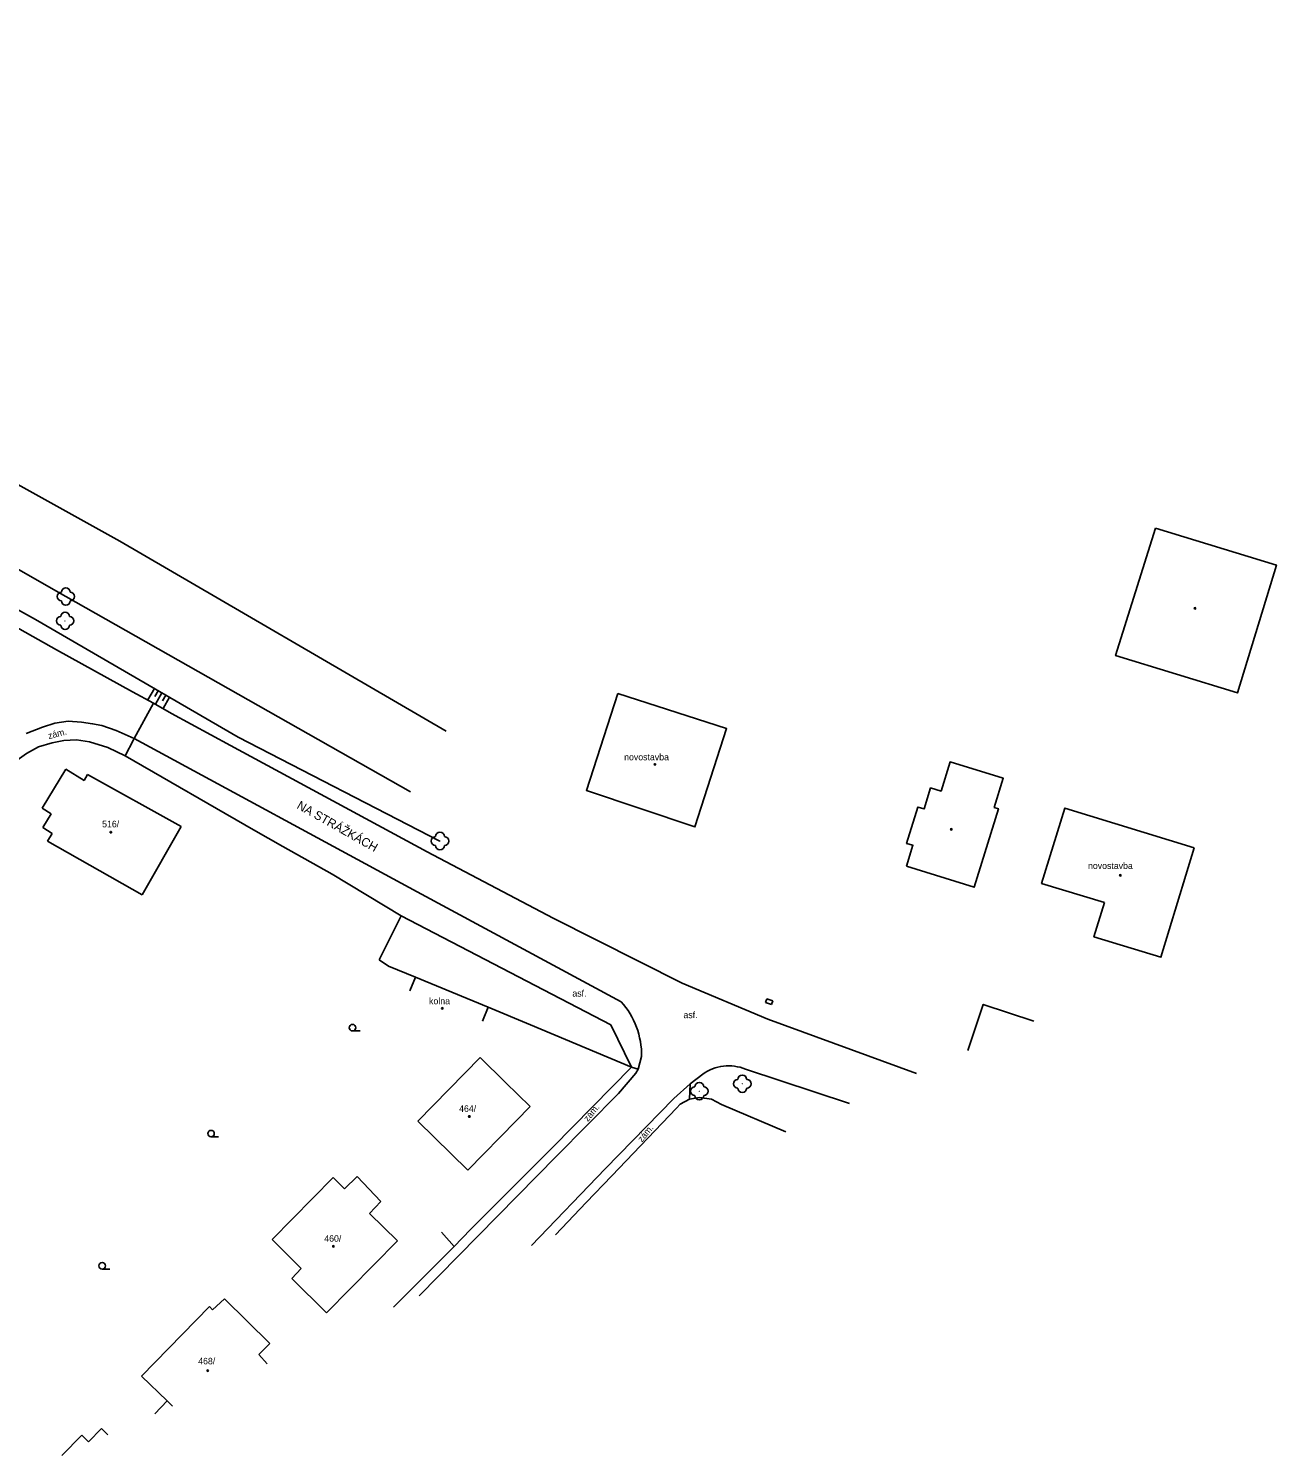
# Model space of a CAD drawing. Extents: x -737488 to -734267, y -1145775 to -1142573.
# Drawn here: x -736465.6 to -736322.7, y -1144292.3 to -1144128.9 of the extents above; entities that cross this region are included whole.
import ezdxf

# ---------------------------------------------------------------- set-up
doc = ezdxf.new("R2010")
doc.units = 0
for name, color, linetype in [('Vrstva 1', 7, 'Continuous'), ('Vrstva 10', 7, 'Continuous'), ('Vrstva 11', 7, 'Continuous'), ('Vrstva 12', 7, 'Continuous'), ('Vrstva 13', 7, 'Continuous'), ('Vrstva 14', 7, 'Continuous'), ('Vrstva 3', 7, 'Continuous'), ('Vrstva 4', 7, 'Continuous'), ('Vrstva 5', 7, 'Continuous'), ('Vrstva 6', 7, 'Continuous'), ('Vrstva 8', 7, 'Continuous'), ('Vrstva 9', 7, 'Continuous')]:
    doc.layers.add(name, color=color, linetype=linetype)

# ---------------------------------------------------------------- blocks, each defined once
blk = doc.blocks.new('3.130')
at = {"layer": 'Vrstva 1'}
blk.add_circle((0, 0), 0.001, dxfattribs=at)
for centre, start, end in [((-1, 0), 90, 270), ((0, 1), 0, 180), ((1, 0), 270, 90), ((0, -1), 180, 360)]:
    blk.add_arc(centre, 1, start, end, dxfattribs=at)
blk = doc.blocks.new('3.040')
at = {"layer": 'Vrstva 1'}
blk.add_line((0, -0.75), (1.75, -0.75), dxfattribs=at)
blk.add_circle((0, 0), 0.75, dxfattribs=at)
blk = doc.blocks.new('4.020')
at = {"layer": 'Vrstva 1'}
blk.add_circle((0, 0), 0.175, dxfattribs=at)

msp = doc.modelspace()

# ---------------------------------------------------------------- linework, layer by layer
at = {"layer": 'Vrstva 10'}
for points in [[(-736462.4, -1144200.02), (-736481.94, -1144189.02), (-736496.2, -1144180.94)], [(-736442.48, -1144210.96), (-736449.24, -1144207.31), (-736451.29, -1144206.13), (-736453.68, -1144204.84), (-736462.4, -1144200.02)], [(-736453.49, -1144210.18), (-736451.29, -1144206.13)], [(-736453.49, -1144210.18), (-736455.57, -1144209.25), (-736457.19, -1144208.69), (-736458.26, -1144208.49), (-736459.52, -1144208.29), (-736461.05, -1144208.2), (-736462.6, -1144208.42), (-736463.99, -1144208.86), (-736465.87, -1144209.59)], [(-736454.55, -1144212.14), (-736453.57, -1144210.31), (-736453.49, -1144210.18)], [(-736421.08, -1144227.71), (-736453.49, -1144210.18)], [(-736419.94, -1144223.15), (-736442.48, -1144210.96)], [(-736405.53, -1144230.73), (-736419.94, -1144223.15)], [(-736397.73, -1144240.31), (-736421.08, -1144227.71)], [(-736398.91, -1144242.95), (-736422.93, -1144230.47)], [(-736390.76, -1144238.2), (-736405.53, -1144230.73)], [(-736380.94, -1144242.31), (-736390.76, -1144238.2)], [(-736396.54, -1144247.81), (-736398.91, -1144242.95)], [(-736363.91, -1144248.54), (-736380.94, -1144242.31)], [(-736396.54, -1144247.81), (-736395.78, -1144248.02)], [(-736395.78, -1144248.02), (-736395.39, -1144246.57)], [(-736396.05, -1144248.48), (-736398.03, -1144250.81)], [(-736396.05, -1144248.48), (-736395.78, -1144248.02)], [(-736389.84, -1144249.7), (-736388.39, -1144248.6)], [(-736383.51, -1144248.04), (-736371.57, -1144251.96)], [(-736398.03, -1144250.81), (-736405.15, -1144257.99)], [(-736391.71, -1144251.37), (-736389.84, -1144249.7)], [(-736389.89, -1144251.47), (-736389.84, -1144249.7)], [(-736399.57, -1144259.44), (-736391.71, -1144251.37)], [(-736405.15, -1144257.99), (-736420.87, -1144273.98)], [(-736408, -1144268.23), (-736399.57, -1144259.44)]]:
    msp.add_lwpolyline(points, dxfattribs=at)
for centre, radius, start, end in [((-736404.68, -1144246.47), 9.29, 359.4064, 41.5852), ((-736385.45, -1144252.65), 5.01, 67.1687, 125.9238)]:
    msp.add_arc(centre, radius, start, end, dxfattribs=at)
at = {"layer": 'Vrstva 11'}
for points in [[(-736455.15, -1144187.56), (-736577.03, -1144119.86)], [(-736461.33, -1144193.92), (-736494.02, -1144175.27)], [(-736464.81, -1144196.55), (-736495.08, -1144179.74)], [(-736417.78, -1144209.32), (-736455.15, -1144187.56)], [(-736421.84, -1144216.29), (-736461.33, -1144193.92)], [(-736441.58, -1144210.01), (-736464.81, -1144196.55)], [(-736418.48, -1144221.91), (-736441.58, -1144210.01)]]:
    msp.add_lwpolyline(points, dxfattribs=at)
at = {"layer": 'Vrstva 12'}
for points in [[(-736451.18, -1144204.45), (-736451.94, -1144205.76)], [(-736450.75, -1144204.7), (-736451.13, -1144205.35)], [(-736450.32, -1144204.95), (-736451.07, -1144206.24)], [(-736449.88, -1144205.2), (-736450.26, -1144205.84)], [(-736449.45, -1144205.45), (-736450.19, -1144206.72)]]:
    msp.add_lwpolyline(points, dxfattribs=at)
at = {"layer": 'Vrstva 4'}
for points in [[(-736398.12, -1144205.01), (-736401.71, -1144216.11), (-736389.29, -1144220.29), (-736385.66, -1144209.04), (-736398.12, -1144205.01)], [(-736332.1, -1144222.67), (-736346.92, -1144218.13), (-736349.58, -1144226.77), (-736342.4, -1144228.94)], [(-736421.27, -1144237.49), (-736412.96, -1144240.94)], [(-736381.22, -1144240.39), (-736381.05, -1144239.96)], [(-736380.53, -1144240.64), (-736381.22, -1144240.39)], [(-736381.05, -1144239.96), (-736380.36, -1144240.21)], [(-736380.53, -1144240.64), (-736380.36, -1144240.21)], [(-736350.46, -1144242.53), (-736356.27, -1144240.62), (-736358.02, -1144245.91)]]:
    msp.add_lwpolyline(points, dxfattribs=at)
at = {"layer": 'Vrstva 5'}
for points in [[(-736336.56, -1144186.08), (-736341.12, -1144200.68), (-736327.16, -1144204.95), (-736322.69, -1144190.32), (-736336.56, -1144186.08)], [(-736365.06, -1144224.8), (-736357.29, -1144227.2), (-736354.53, -1144218.21), (-736355.01, -1144218.06), (-736353.98, -1144214.72), (-736360.06, -1144212.86), (-736361.1, -1144216.2), (-736362.3, -1144215.83), (-736363.04, -1144218.23), (-736363.75, -1144218.02), (-736365.04, -1144222.18), (-736364.32, -1144222.4), (-736365.06, -1144224.8)], [(-736464.02, -1144218.16), (-736461.32, -1144213.7)], [(-736461.32, -1144213.7), (-736459.24, -1144214.99)], [(-736459.24, -1144214.99), (-736458.84, -1144214.29)], [(-736458.84, -1144214.29), (-736448.1, -1144220.25)], [(-736463.02, -1144218.79), (-736464.02, -1144218.16)], [(-736463.95, -1144220.36), (-736463.02, -1144218.79)], [(-736462.88, -1144221.04), (-736463.95, -1144220.36)], [(-736463.43, -1144221.93), (-736462.88, -1144221.04)], [(-736448.1, -1144220.25), (-736452.58, -1144228.07)], [(-736452.58, -1144228.07), (-736463.43, -1144221.93)], [(-736342.4, -1144228.94), (-736343.59, -1144232.86), (-736335.93, -1144235.21), (-736332.1, -1144222.67)], [(-736421.92, -1144239.06), (-736421.27, -1144237.49)], [(-736413.62, -1144242.53), (-736412.96, -1144240.94)], [(-736421.02, -1144253.98), (-736413.89, -1144246.7)], [(-736413.89, -1144246.7), (-736410.96, -1144249.56)], [(-736410.96, -1144249.56), (-736408.15, -1144252.32)], [(-736408.15, -1144252.32), (-736409.75, -1144253.96)], [(-736415.28, -1144259.6), (-736421.02, -1144253.98)], [(-736409.75, -1144253.96), (-736415.28, -1144259.6)], [(-736430.72, -1144260.43), (-736437.71, -1144267.53)], [(-736429.4, -1144261.72), (-736430.72, -1144260.43)], [(-736427.96, -1144260.3), (-736429.4, -1144261.72)], [(-736425.24, -1144263.18), (-736427.96, -1144260.3)], [(-736426.54, -1144264.54), (-736425.24, -1144263.18)], [(-736423.36, -1144267.67), (-736426.54, -1144264.54)], [(-736437.71, -1144267.53), (-736434.37, -1144270.87)], [(-736431.47, -1144275.92), (-736423.36, -1144267.67)], [(-736434.37, -1144270.87), (-736435.45, -1144272)], [(-736435.45, -1144272), (-736431.47, -1144275.92)], [(-736444.88, -1144275.2), (-736452.65, -1144283.18)], [(-736444.52, -1144275.59), (-736444.88, -1144275.2)], [(-736443.17, -1144274.34), (-736444.52, -1144275.59)], [(-736437.96, -1144279.43), (-736443.17, -1144274.34)], [(-736439.23, -1144280.7), (-736437.96, -1144279.43)], [(-736438.27, -1144281.75), (-736439.23, -1144280.7)], [(-736452.65, -1144283.18), (-736449.73, -1144286.02)], [(-736449.73, -1144286.02), (-736451.14, -1144287.5)], [(-736449.73, -1144286.02), (-736449.13, -1144286.6)], [(-736459.49, -1144289.94), (-736461.8, -1144292.26)], [(-736458.73, -1144290.69), (-736459.49, -1144289.94)], [(-736457.24, -1144289.17), (-736458.73, -1144290.69)], [(-736456.51, -1144289.89), (-736457.24, -1144289.17)]]:
    msp.add_lwpolyline(points, dxfattribs=at)
at = {"layer": 'Vrstva 9'}
for points in [[(-736454.55, -1144212.14), (-736456.51, -1144211.22), (-736458.63, -1144210.57), (-736460.12, -1144210.34), (-736461.57, -1144210.4)], [(-736461.57, -1144210.4), (-736462.9, -1144210.65), (-736464.47, -1144211.12), (-736465.82, -1144211.88), (-736467.87, -1144213.34)], [(-736439.82, -1144220.62), (-736454.55, -1144212.14)], [(-736436.49, -1144222.52), (-736439.82, -1144220.62)], [(-736430.83, -1144225.71), (-736436.49, -1144222.52)], [(-736422.93, -1144230.47), (-736430.83, -1144225.71)], [(-736425.46, -1144235.5), (-736422.93, -1144230.47)], [(-736424.39, -1144236.24), (-736425.46, -1144235.5)], [(-736421.27, -1144237.49), (-736424.39, -1144236.24)], [(-736408.13, -1144242.95), (-736412.96, -1144240.94)], [(-736396.54, -1144247.81), (-736408.13, -1144242.95)], [(-736405.53, -1144256.92), (-736396.54, -1144247.81)], [(-736391.38, -1144252.48), (-736398.79, -1144260.26)], [(-736391.38, -1144252.48), (-736390.99, -1144252.04)], [(-736386.25, -1144252.07), (-736387.37, -1144251.48), (-736388.78, -1144251.28), (-736389.89, -1144251.47), (-736390.99, -1144252.04)], [(-736378.87, -1144255.22), (-736386.25, -1144252.07)], [(-736412.36, -1144263.76), (-736405.53, -1144256.92)], [(-736401.73, -1144263.29), (-736398.79, -1144260.26)], [(-736412.36, -1144263.76), (-736415, -1144266.4)], [(-736401.73, -1144263.29), (-736405.27, -1144267.01)], [(-736416.84, -1144268.32), (-736418.32, -1144266.71)], [(-736416.84, -1144268.32), (-736415, -1144266.4)], [(-736416.84, -1144268.32), (-736418.07, -1144269.55)], [(-736418.07, -1144269.55), (-736419.58, -1144271.06)], [(-736423.79, -1144275.28), (-736419.58, -1144271.06)]]:
    msp.add_lwpolyline(points, dxfattribs=at)

# ---------------------------------------------------------------- block references
at = {"layer": 'Vrstva 11', "xscale": 0.5, "yscale": 0.5}
for p in [(-736461.33, -1144193.92), (-736461.41, -1144196.7), (-736418.48, -1144221.91), (-736388.78, -1144250.55), (-736383.86, -1144249.7)]:
    msp.add_blockref('3.130', p, dxfattribs=at)
at = {"layer": 'Vrstva 3', "xscale": 0.5, "yscale": 0.5}
for p in [(-736428.49, -1144243.28), (-736444.7, -1144255.41), (-736457.16, -1144270.54)]:
    msp.add_blockref('3.040', p, dxfattribs=at)
at = {"layer": 'Vrstva 8', "xscale": 0.5, "yscale": 0.5}
for p in [(-736332.02, -1144195.26), (-736393.87, -1144213.14), (-736456.17, -1144220.9), (-736359.93, -1144220.57), (-736340.57, -1144225.83), (-736418.22, -1144241.07), (-736415.12, -1144253.45), (-736430.68, -1144268.31), (-736445.07, -1144282.54)]:
    msp.add_blockref('4.020', p, dxfattribs=at)

# ---------------------------------------------------------------- texts
at = {"layer": 'Vrstva 13'}
msp.add_text('NA STRÁŽKÁCH', height=1, rotation=330.564, dxfattribs=at).set_placement((-736434.96, -1144218.12))
at = {"layer": 'Vrstva 14'}
for rotation, p in [(14.718, (-736463.26, -1144210.25)), (50.519, (-736401.54, -1144254.09)), (50.519, (-736395.35, -1144256.45))]:
    msp.add_text('zám.', height=0.75, rotation=rotation, dxfattribs=at).set_placement(p)
for s, p in [('novostavba', (-736397.39, -1144212.67)), ('novostavba', (-736344.27, -1144225.11)), ('asf.', (-736403.32, -1144239.72)), ('kolna', (-736419.73, -1144240.6)), ('asf.', (-736390.6, -1144242.19))]:
    msp.add_text(s, height=0.75, dxfattribs=at).set_placement(p)
at = {"layer": 'Vrstva 6'}
for s, p in [('516/', (-736457.17, -1144220.34)), ('464/', (-736416.29, -1144252.92)), ('460/', (-736431.73, -1144267.79)), ('468/', (-736446.17, -1144281.83))]:
    msp.add_text(s, height=0.75, dxfattribs=at).set_placement(p)

doc.saveas('drawing.dxf')
